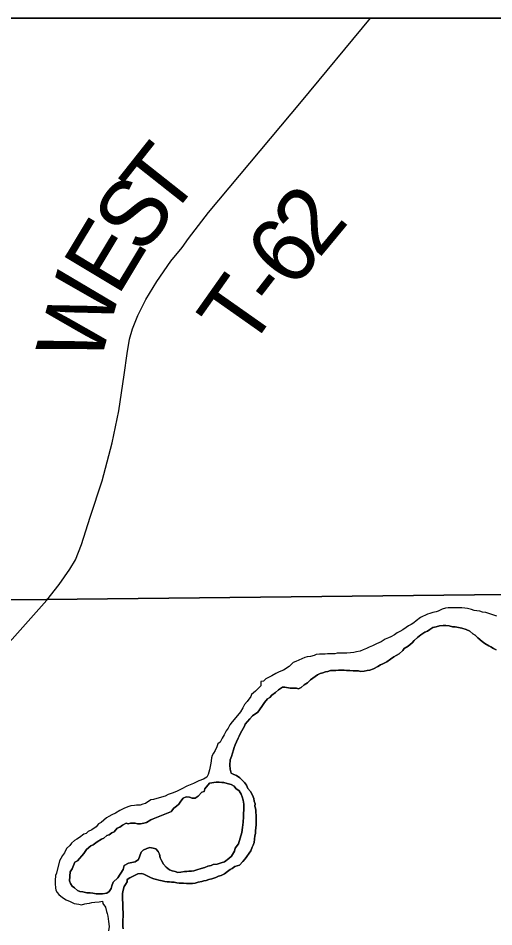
# Model space of a CAD drawing. Extents: x 0 to 34, y 0 to 22.
# Drawn here: x 4.009 to 4.417, y 20.12 to 20.9 of the extents above; entities that cross this region are included whole.
import ezdxf

# ---------------------------------------------------------------- set-up
doc = ezdxf.new("R2010")
doc.units = 0
for name, color, linetype in [('GM_X_Corporation', 7, 'Continuous'), ('GM_X_Major_River', 7, 'Continuous'), ('GM_X_Township_Road', 7, 'Continuous'), ('GM_X_Township_Road_Text', 7, 'Continuous'), ('SH_Data', 7, 'Continuous')]:
    doc.layers.add(name, color=color, linetype=linetype)

msp = doc.modelspace()

# ---------------------------------------------------------------- linework, layer by layer
at = {"layer": 'GM_X_Corporation'}
for points in [[(6.97994, 20.9), (2.1, 20.9)], [(6.97994, 20.9), (2.1, 20.9)], [(5.94533, 20.41578), (5.00335, 20.41162), (4.03341, 20.40117), (3.32712, 20.397)], [(3.32712, 20.397), (4.03341, 20.40117), (5.00335, 20.41162), (5.94533, 20.41578)], [(5.94533, 20.41578), (5.00335, 20.41162), (4.03341, 20.40117), (3.32712, 20.397)], [(3.32712, 20.397), (4.03341, 20.40117), (5.00335, 20.41162), (5.94533, 20.41578)]]:
    msp.add_lwpolyline(points, dxfattribs=at)
at = {"layer": 'GM_X_Major_River'}
for points in [[(4.41945, 20.38683), (4.41261, 20.38912), (4.40995, 20.38988), (4.40729, 20.39026), (4.40501, 20.39103), (4.40235, 20.39141), (4.40007, 20.39179), (4.39779, 20.39255), (4.39437, 20.39332), (4.3921, 20.3937), (4.38944, 20.39408), (4.38374, 20.39409), (4.38146, 20.39409), (4.37766, 20.39409), (4.37538, 20.39372), (4.37272, 20.39295), (4.36929, 20.39106), (4.3674, 20.39068), (4.36473, 20.38992), (4.36207, 20.38916), (4.36017, 20.3884), (4.35409, 20.38575), (4.35029, 20.38271), (4.34838, 20.38119), (4.3461, 20.37967), (4.34382, 20.37853), (4.34192, 20.37701)], [(4.41945, 20.38683), (4.41261, 20.38912), (4.40995, 20.38988), (4.40729, 20.39026), (4.40501, 20.39103), (4.40235, 20.39141), (4.40007, 20.39179), (4.39779, 20.39255), (4.39437, 20.39332), (4.3921, 20.3937), (4.38944, 20.39408), (4.38374, 20.39409), (4.38146, 20.39409), (4.37766, 20.39409), (4.37538, 20.39372), (4.37272, 20.39295), (4.36929, 20.39106), (4.3674, 20.39068), (4.36473, 20.38992), (4.36207, 20.38916), (4.36017, 20.3884), (4.35409, 20.38575), (4.35029, 20.38271), (4.34838, 20.38119), (4.3461, 20.37967), (4.34382, 20.37853), (4.34192, 20.37701)], [(4.34192, 20.37701), (4.33888, 20.37511), (4.33622, 20.37359), (4.33394, 20.37245), (4.33166, 20.37093), (4.32862, 20.36903), (4.32671, 20.36827), (4.32367, 20.36713), (4.32025, 20.36486), (4.31645, 20.36296), (4.31303, 20.36144), (4.30998, 20.3603), (4.3077, 20.35916), (4.30504, 20.35802), (4.30238, 20.35688), (4.29934, 20.35612), (4.29706, 20.35575), (4.29402, 20.35537), (4.29098, 20.35499), (4.28794, 20.35499), (4.2849, 20.35499), (4.28262, 20.355), (4.28072, 20.35462), (4.27654, 20.35462), (4.27426, 20.35462), (4.27236, 20.35424), (4.27046, 20.35425), (4.26742, 20.35425), (4.26476, 20.35387), (4.26286, 20.35311), (4.25982, 20.35235), (4.25678, 20.35198), (4.25488, 20.35122), (4.24728, 20.3478), (4.245, 20.34704), (4.24157, 20.34362), (4.23663, 20.34058), (4.23283, 20.33907), (4.23017, 20.33755), (4.22674, 20.33565), (4.2237, 20.33413), (4.22142, 20.33299), (4.21952, 20.33109), (4.21724, 20.33071), (4.21724, 20.32691), (4.21267, 20.32235), (4.20925, 20.31969), (4.20849, 20.31779), (4.20544, 20.31361), (4.20316, 20.31094), (4.20164, 20.30828), (4.19973, 20.30486), (4.19707, 20.30144), (4.19251, 20.29612), (4.1906, 20.29346), (4.18908, 20.2908), (4.18756, 20.28852), (4.18565, 20.2851), (4.18413, 20.28205), (4.18223, 20.27863), (4.18032, 20.27712), (4.17956, 20.27483), (4.17804, 20.27141), (4.17652, 20.26913), (4.17537, 20.26723), (4.17499, 20.26533), (4.17461, 20.26267), (4.17423, 20.26077), (4.17308, 20.25506), (4.17194, 20.25088), (4.17079, 20.2486), (4.16813, 20.24708), (4.16395, 20.24556), (4.15939, 20.24328), (4.15369, 20.24101), (4.14951, 20.23873), (4.14494, 20.23645), (4.14114, 20.23493), (4.13772, 20.23379), (4.13506, 20.23227), (4.13202, 20.23151), (4.12518, 20.22962), (4.1229, 20.22924), (4.11833, 20.2262), (4.11605, 20.22544), (4.11377, 20.22469), (4.11073, 20.22469), (4.10883, 20.22431), (4.10579, 20.22393), (4.10313, 20.22317), (4.09971, 20.22165), (4.09629, 20.22014), (4.09249, 20.21786), (4.08944, 20.21634), (4.08678, 20.21482), (4.08488, 20.21368), (4.0826, 20.21178), (4.08032, 20.20988), (4.07804, 20.20874), (4.07613, 20.20608), (4.07233, 20.20342)], [(4.34192, 20.37701), (4.33888, 20.37511), (4.33622, 20.37359), (4.33394, 20.37245), (4.33166, 20.37093), (4.32862, 20.36903), (4.32671, 20.36827), (4.32367, 20.36713), (4.32025, 20.36486), (4.31645, 20.36296), (4.31303, 20.36144), (4.30998, 20.3603), (4.3077, 20.35916), (4.30504, 20.35802), (4.30238, 20.35688), (4.29934, 20.35612), (4.29706, 20.35575), (4.29402, 20.35537), (4.29098, 20.35499), (4.28794, 20.35499), (4.2849, 20.35499), (4.28262, 20.355), (4.28072, 20.35462), (4.27654, 20.35462), (4.27426, 20.35462), (4.27236, 20.35424), (4.27046, 20.35425), (4.26742, 20.35425), (4.26476, 20.35387), (4.26286, 20.35311), (4.25982, 20.35235), (4.25678, 20.35198), (4.25488, 20.35122), (4.24728, 20.3478), (4.245, 20.34704), (4.24157, 20.34362), (4.23663, 20.34058), (4.23283, 20.33907), (4.23017, 20.33755), (4.22674, 20.33565), (4.2237, 20.33413), (4.22142, 20.33299), (4.21952, 20.33109), (4.21724, 20.33071), (4.21724, 20.32691), (4.21267, 20.32235), (4.20925, 20.31969), (4.20849, 20.31779), (4.20544, 20.31361), (4.20316, 20.31094), (4.20164, 20.30828), (4.19973, 20.30486), (4.19707, 20.30144), (4.19251, 20.29612), (4.1906, 20.29346), (4.18908, 20.2908), (4.18756, 20.28852), (4.18565, 20.2851), (4.18413, 20.28205), (4.18223, 20.27863), (4.18032, 20.27712), (4.17956, 20.27483), (4.17804, 20.27141), (4.17652, 20.26913), (4.17537, 20.26723), (4.17499, 20.26533), (4.17461, 20.26267), (4.17423, 20.26077), (4.17308, 20.25506), (4.17194, 20.25088), (4.17079, 20.2486), (4.16813, 20.24708), (4.16395, 20.24556), (4.15939, 20.24328), (4.15369, 20.24101), (4.14951, 20.23873), (4.14494, 20.23645), (4.14114, 20.23493), (4.13772, 20.23379), (4.13506, 20.23227), (4.13202, 20.23151), (4.12518, 20.22962), (4.1229, 20.22924), (4.11833, 20.2262), (4.11605, 20.22544), (4.11377, 20.22469), (4.11073, 20.22469), (4.10883, 20.22431), (4.10579, 20.22393), (4.10313, 20.22317), (4.09971, 20.22165), (4.09629, 20.22014), (4.09249, 20.21786), (4.08944, 20.21634), (4.08678, 20.21482), (4.08488, 20.21368), (4.0826, 20.21178), (4.08032, 20.20988), (4.07804, 20.20874), (4.07613, 20.20608), (4.07233, 20.20342)], [(4.26588, 20.33637), (4.26816, 20.33751), (4.27044, 20.33827), (4.27272, 20.33903), (4.27462, 20.33941), (4.27691, 20.34017), (4.2788, 20.34017), (4.28147, 20.34017), (4.28375, 20.34055), (4.28602, 20.34054), (4.28869, 20.34054), (4.29058, 20.34016), (4.29363, 20.34015), (4.29628, 20.33977), (4.29856, 20.33977), (4.30084, 20.33977), (4.30274, 20.33939), (4.30578, 20.33976), (4.30844, 20.34014), (4.31072, 20.34052), (4.31376, 20.34166), (4.31757, 20.34356), (4.31985, 20.34508), (4.32175, 20.34584), (4.32517, 20.34774), (4.32821, 20.35002), (4.33126, 20.35191), (4.33316, 20.35305), (4.33582, 20.35457), (4.33886, 20.35723), (4.34, 20.35913), (4.34342, 20.36103), (4.34685, 20.36407), (4.34875, 20.36597), (4.35141, 20.36863), (4.35445, 20.37091), (4.35788, 20.37319), (4.36015, 20.37395), (4.36206, 20.37547), (4.36472, 20.37699), (4.36738, 20.37775), (4.37042, 20.37851), (4.37346, 20.37888), (4.37574, 20.37888), (4.37878, 20.3785), (4.38144, 20.37773), (4.38372, 20.37773), (4.38676, 20.37697), (4.38942, 20.37659), (4.39322, 20.37544), (4.39625, 20.37392), (4.39891, 20.37164), (4.40081, 20.37049), (4.40309, 20.36821), (4.40688, 20.36516), (4.40916, 20.36326), (4.41258, 20.36136), (4.41448, 20.36059), (4.41676, 20.35907), (4.41903, 20.35793)], [(4.41903, 20.35793), (4.41676, 20.35907), (4.41448, 20.36059), (4.41258, 20.36136), (4.40916, 20.36326), (4.40688, 20.36516), (4.40309, 20.36821), (4.40081, 20.37049), (4.39891, 20.37164), (4.39625, 20.37392), (4.39322, 20.37544), (4.38942, 20.37659), (4.38676, 20.37697), (4.38372, 20.37773), (4.38144, 20.37773), (4.37878, 20.3785), (4.37574, 20.37888), (4.37346, 20.37888), (4.37042, 20.37851), (4.36738, 20.37775), (4.36472, 20.37699), (4.36206, 20.37547), (4.36015, 20.37395), (4.35788, 20.37319), (4.35445, 20.37091), (4.35141, 20.36863), (4.34875, 20.36597), (4.34685, 20.36407), (4.34342, 20.36103), (4.34, 20.35913), (4.33886, 20.35723), (4.33582, 20.35457), (4.33316, 20.35305), (4.33126, 20.35191), (4.32821, 20.35002), (4.32517, 20.34774), (4.32175, 20.34584), (4.31985, 20.34508), (4.31757, 20.34356), (4.31376, 20.34166), (4.31072, 20.34052), (4.30844, 20.34014), (4.30578, 20.33976), (4.30274, 20.33939), (4.30084, 20.33977), (4.29856, 20.33977), (4.29628, 20.33977), (4.29363, 20.34015), (4.29058, 20.34016), (4.28869, 20.34054), (4.28602, 20.34054), (4.28375, 20.34055), (4.28147, 20.34017), (4.2788, 20.34017), (4.27691, 20.34017), (4.27462, 20.33941), (4.27272, 20.33903), (4.27044, 20.33827), (4.26816, 20.33751), (4.26588, 20.33637)], [(4.12548, 20.16154), (4.12776, 20.16078), (4.12966, 20.1604), (4.1327, 20.15963), (4.13498, 20.15925), (4.13688, 20.15887), (4.13878, 20.15887), (4.14068, 20.15849), (4.14296, 20.15848), (4.14524, 20.1581), (4.14714, 20.15772), (4.14904, 20.15772), (4.15094, 20.15772), (4.1536, 20.15733), (4.15664, 20.15733), (4.15854, 20.15733), (4.16082, 20.15771), (4.16348, 20.15847), (4.16652, 20.15923), (4.16842, 20.1596), (4.17032, 20.15998), (4.1726, 20.16074), (4.17526, 20.1615), (4.17868, 20.16264), (4.18096, 20.16378), (4.18324, 20.16416), (4.1859, 20.16568), (4.18857, 20.16758), (4.19085, 20.16947), (4.19275, 20.17023), (4.19503, 20.17213), (4.19883, 20.17327), (4.20187, 20.17631), (4.20378, 20.17859), (4.20872, 20.18543), (4.20987, 20.18848), (4.21063, 20.19037), (4.21139, 20.19266), (4.21177, 20.19532), (4.21216, 20.19836), (4.21254, 20.20026), (4.21254, 20.20255), (4.21292, 20.20521), (4.21331, 20.20787), (4.21331, 20.21167), (4.21331, 20.21433), (4.21332, 20.21624), (4.21294, 20.21814), (4.21294, 20.22004), (4.21256, 20.22194), (4.21218, 20.22384), (4.21219, 20.22575), (4.21143, 20.22803), (4.21105, 20.23031), (4.20992, 20.23335), (4.2084, 20.2364), (4.20612, 20.23906), (4.20498, 20.24173), (4.20309, 20.24401), (4.20157, 20.24591), (4.19929, 20.24819), (4.19625, 20.2501), (4.19397, 20.25086), (4.1917, 20.25201), (4.19094, 20.25543), (4.19056, 20.25885), (4.19095, 20.26341), (4.19209, 20.26646), (4.19362, 20.27216), (4.19438, 20.27406), (4.19514, 20.27634), (4.19629, 20.279), (4.19781, 20.28205), (4.19857, 20.28395), (4.19933, 20.28585), (4.20086, 20.28851), (4.202, 20.29041), (4.20314, 20.29231), (4.2039, 20.29421), (4.20771, 20.29877), (4.20999, 20.30143), (4.21455, 20.30447), (4.21798, 20.30941), (4.22026, 20.31283), (4.22292, 20.31587), (4.22482, 20.31701), (4.22673, 20.31891), (4.22977, 20.32119), (4.23243, 20.32347), (4.23585, 20.32575), (4.23775, 20.32575), (4.24231, 20.32498), (4.24459, 20.32498), (4.24763, 20.32498), (4.24953, 20.3246), (4.25181, 20.32574), (4.25447, 20.32802), (4.25714, 20.32954), (4.2598, 20.3322), (4.2617, 20.33372), (4.26588, 20.33637)], [(4.26588, 20.33637), (4.2617, 20.33372), (4.2598, 20.3322), (4.25714, 20.32954), (4.25447, 20.32802), (4.25181, 20.32574), (4.24953, 20.3246), (4.24763, 20.32498), (4.24459, 20.32498), (4.24231, 20.32498), (4.23775, 20.32575), (4.23585, 20.32575), (4.23243, 20.32347), (4.22977, 20.32119), (4.22673, 20.31891), (4.22482, 20.31701), (4.22292, 20.31587), (4.22026, 20.31283), (4.21798, 20.30941), (4.21455, 20.30447), (4.20999, 20.30143), (4.20771, 20.29877), (4.2039, 20.29421), (4.20314, 20.29231), (4.202, 20.29041), (4.20086, 20.28851), (4.19933, 20.28585), (4.19857, 20.28395), (4.19781, 20.28205), (4.19629, 20.279), (4.19514, 20.27634), (4.19438, 20.27406), (4.19362, 20.27216), (4.19209, 20.26646), (4.19095, 20.26341), (4.19056, 20.25885), (4.19094, 20.25543), (4.1917, 20.25201), (4.19397, 20.25086), (4.19625, 20.2501), (4.19929, 20.24819), (4.20157, 20.24591), (4.20309, 20.24401), (4.20498, 20.24173), (4.20612, 20.23906), (4.2084, 20.2364), (4.20992, 20.23335), (4.21105, 20.23031), (4.21143, 20.22803), (4.21219, 20.22575), (4.21218, 20.22384), (4.21256, 20.22194), (4.21294, 20.22004), (4.21294, 20.21814), (4.21332, 20.21624), (4.21331, 20.21433), (4.21331, 20.21167), (4.21331, 20.20787), (4.21292, 20.20521), (4.21254, 20.20255), (4.21254, 20.20026), (4.21216, 20.19836), (4.21177, 20.19532), (4.21139, 20.19266), (4.21063, 20.19037), (4.20987, 20.18848), (4.20872, 20.18543), (4.20378, 20.17859), (4.20187, 20.17631), (4.19883, 20.17327), (4.19503, 20.17213), (4.19275, 20.17023), (4.19085, 20.16947), (4.18857, 20.16758), (4.1859, 20.16568), (4.18324, 20.16416), (4.18096, 20.16378), (4.17868, 20.16264), (4.17526, 20.1615), (4.1726, 20.16074), (4.17032, 20.15998), (4.16842, 20.1596), (4.16652, 20.15923), (4.16348, 20.15847), (4.16082, 20.15771), (4.15854, 20.15733), (4.15664, 20.15733), (4.1536, 20.15733), (4.15094, 20.15772), (4.14904, 20.15772), (4.14714, 20.15772), (4.14524, 20.1581), (4.14296, 20.15848), (4.14068, 20.15849), (4.13878, 20.15887), (4.13688, 20.15887), (4.13498, 20.15925), (4.1327, 20.15963), (4.12966, 20.1604), (4.12776, 20.16078), (4.12548, 20.16154)], [(4.1035, 20.20872), (4.1016, 20.2091), (4.09856, 20.20758), (4.09627, 20.20568), (4.09399, 20.20492), (4.09133, 20.20188), (4.08943, 20.20075), (4.08715, 20.19923), (4.08525, 20.19847), (4.08258, 20.19619), (4.08068, 20.19543), (4.07688, 20.19315), (4.07346, 20.19049), (4.07156, 20.18973), (4.06776, 20.18669), (4.06547, 20.18327), (4.06014, 20.17681), (4.05786, 20.17567), (4.05558, 20.16997), (4.05367, 20.16731), (4.05329, 20.1597), (4.05404, 20.15742), (4.05556, 20.15513), (4.05746, 20.15361), (4.06012, 20.15133), (4.06202, 20.15056), (4.06467, 20.15018), (4.06809, 20.14942), (4.07075, 20.14942), (4.07303, 20.14903), (4.07607, 20.14865), (4.07835, 20.14865), (4.08139, 20.14865), (4.08519, 20.14902), (4.08709, 20.15054), (4.089, 20.1532), (4.08938, 20.15549), (4.09052, 20.15853), (4.09471, 20.16233), (4.09927, 20.16955), (4.10004, 20.17297), (4.10384, 20.17487), (4.10954, 20.17601), (4.1122, 20.17791), (4.11449, 20.18437), (4.11639, 20.18589), (4.11943, 20.18741), (4.12209, 20.18817), (4.12475, 20.18779), (4.12703, 20.18702), (4.12931, 20.18474), (4.13044, 20.18246), (4.13082, 20.17941), (4.13196, 20.17713), (4.13386, 20.17408), (4.13613, 20.17142), (4.13879, 20.16914), (4.14107, 20.16837), (4.14373, 20.16761), (4.14601, 20.16685), (4.14867, 20.16723), (4.15171, 20.1676), (4.15361, 20.1676), (4.15551, 20.16798), (4.15779, 20.16798), (4.15969, 20.16836), (4.16235, 20.16912), (4.16615, 20.17026), (4.16919, 20.17101), (4.17185, 20.17215), (4.17451, 20.17291), (4.17641, 20.17367), (4.17983, 20.17405), (4.18325, 20.17519), (4.18591, 20.17594), (4.18972, 20.17898), (4.192, 20.18088), (4.19466, 20.18506), (4.19505, 20.18773), (4.19809, 20.19153), (4.20076, 20.20103), (4.20153, 20.2056), (4.20191, 20.21016), (4.2023, 20.21472), (4.2023, 20.21701), (4.20268, 20.22119), (4.20269, 20.22537), (4.20193, 20.2288), (4.20117, 20.23184), (4.20042, 20.23412), (4.19852, 20.23679), (4.19586, 20.23907), (4.19434, 20.24097), (4.19169, 20.2425), (4.18827, 20.24326), (4.18561, 20.24402), (4.18371, 20.24402), (4.18143, 20.2444), (4.17991, 20.24441), (4.17877, 20.24441)], [(4.17877, 20.24441), (4.17991, 20.24441), (4.18143, 20.2444), (4.18371, 20.24402), (4.18561, 20.24402), (4.18827, 20.24326), (4.19169, 20.2425), (4.19434, 20.24097), (4.19586, 20.23907), (4.19852, 20.23679), (4.20042, 20.23412), (4.20117, 20.23184), (4.20193, 20.2288), (4.20269, 20.22537), (4.20268, 20.22119), (4.2023, 20.21701), (4.2023, 20.21472), (4.20191, 20.21016), (4.20153, 20.2056), (4.20076, 20.20103), (4.19809, 20.19153), (4.19505, 20.18773), (4.19466, 20.18506), (4.192, 20.18088), (4.18972, 20.17898), (4.18591, 20.17594), (4.18325, 20.17519), (4.17983, 20.17405), (4.17641, 20.17367), (4.17451, 20.17291), (4.17185, 20.17215), (4.16919, 20.17101), (4.16615, 20.17026), (4.16235, 20.16912), (4.15969, 20.16836), (4.15779, 20.16798), (4.15551, 20.16798), (4.15361, 20.1676), (4.15171, 20.1676), (4.14867, 20.16723), (4.14601, 20.16685), (4.14373, 20.16761), (4.14107, 20.16837), (4.13879, 20.16914), (4.13613, 20.17142), (4.13386, 20.17408), (4.13196, 20.17713), (4.13082, 20.17941), (4.13044, 20.18246), (4.12931, 20.18474), (4.12703, 20.18702), (4.12475, 20.18779), (4.12209, 20.18817), (4.11943, 20.18741), (4.11639, 20.18589), (4.11449, 20.18437), (4.1122, 20.17791), (4.10954, 20.17601), (4.10384, 20.17487), (4.10004, 20.17297), (4.09927, 20.16955), (4.09471, 20.16233), (4.09052, 20.15853), (4.08938, 20.15549), (4.089, 20.1532), (4.08709, 20.15054), (4.08519, 20.14902), (4.08139, 20.14865), (4.07835, 20.14865), (4.07607, 20.14865), (4.07303, 20.14903), (4.07075, 20.14942), (4.06809, 20.14942), (4.06467, 20.15018), (4.06202, 20.15056), (4.06012, 20.15133), (4.05746, 20.15361), (4.05556, 20.15513), (4.05404, 20.15742), (4.05329, 20.1597), (4.05367, 20.16731), (4.05558, 20.16997), (4.05786, 20.17567), (4.06014, 20.17681), (4.06547, 20.18327), (4.06776, 20.18669), (4.07156, 20.18973), (4.07346, 20.19049), (4.07688, 20.19315), (4.08068, 20.19543), (4.08258, 20.19619), (4.08525, 20.19847), (4.08715, 20.19923), (4.08943, 20.20075), (4.09133, 20.20188), (4.09399, 20.20492), (4.09627, 20.20568), (4.09856, 20.20758), (4.1016, 20.2091), (4.1035, 20.20872)], [(4.17877, 20.24441), (4.17307, 20.24365), (4.16926, 20.23871), (4.1685, 20.23643), (4.1666, 20.23567), (4.16356, 20.23225), (4.1609, 20.23073), (4.15823, 20.23073), (4.15596, 20.2315), (4.1533, 20.23188), (4.15064, 20.23074), (4.14873, 20.22808), (4.14683, 20.22542), (4.14493, 20.2239), (4.14265, 20.222), (4.14074, 20.21934), (4.14056, 20.21923)], [(4.14056, 20.21923), (4.14074, 20.21934), (4.14265, 20.222), (4.14493, 20.2239), (4.14683, 20.22542), (4.14873, 20.22808), (4.15064, 20.23074), (4.1533, 20.23188), (4.15596, 20.2315), (4.15823, 20.23073), (4.1609, 20.23073), (4.16356, 20.23225), (4.1666, 20.23567), (4.1685, 20.23643), (4.16926, 20.23871), (4.17307, 20.24365), (4.17877, 20.24441)], [(4.14056, 20.21923), (4.12478, 20.21289), (4.12288, 20.21213), (4.11908, 20.20985), (4.1168, 20.20909), (4.11414, 20.20871), (4.11147, 20.20871), (4.10958, 20.20909), (4.1073, 20.2091), (4.1054, 20.2091), (4.1035, 20.20872)], [(4.1035, 20.20872), (4.1054, 20.2091), (4.1073, 20.2091), (4.10958, 20.20909), (4.11147, 20.20871), (4.11414, 20.20871), (4.1168, 20.20909), (4.11908, 20.20985), (4.12288, 20.21213), (4.12478, 20.21289), (4.14056, 20.21923)], [(4.07233, 20.20342), (4.06929, 20.2019), (4.06739, 20.20038), (4.06549, 20.19962), (4.06169, 20.19696), (4.0594, 20.19544), (4.0575, 20.1943), (4.05484, 20.19203), (4.05332, 20.19012), (4.05066, 20.18746), (4.04875, 20.18366), (4.04723, 20.18138), (4.04571, 20.17872), (4.04457, 20.17682), (4.04189, 20.16617), (4.04113, 20.16427), (4.04075, 20.16009), (4.04074, 20.15705), (4.04112, 20.15362), (4.0415, 20.15172), (4.04264, 20.14982), (4.04415, 20.14792), (4.04719, 20.14525), (4.05023, 20.14335), (4.05365, 20.14182), (4.05707, 20.1403), (4.06124, 20.13954), (4.06352, 20.13915), (4.06618, 20.13991), (4.06808, 20.14029), (4.07037, 20.14067), (4.07226, 20.14105), (4.07493, 20.14143), (4.07872, 20.1418), (4.08139, 20.14218), (4.08176, 20.14028), (4.08404, 20.13723), (4.0848, 20.13343), (4.08555, 20.13153), (4.08593, 20.12925), (4.08631, 20.12696), (4.08669, 20.12468), (4.08706, 20.1205), (4.08668, 20.11669)], [(4.07233, 20.20342), (4.06929, 20.2019), (4.06739, 20.20038), (4.06549, 20.19962), (4.06169, 20.19696), (4.0594, 20.19544), (4.0575, 20.1943), (4.05484, 20.19203), (4.05332, 20.19012), (4.05066, 20.18746), (4.04875, 20.18366), (4.04723, 20.18138), (4.04571, 20.17872), (4.04457, 20.17682), (4.04189, 20.16617), (4.04113, 20.16427), (4.04075, 20.16009), (4.04074, 20.15705), (4.04112, 20.15362), (4.0415, 20.15172), (4.04264, 20.14982), (4.04415, 20.14792), (4.04719, 20.14525), (4.05023, 20.14335), (4.05365, 20.14182), (4.05707, 20.1403), (4.06124, 20.13954), (4.06352, 20.13915), (4.06618, 20.13991), (4.06808, 20.14029), (4.07037, 20.14067), (4.07226, 20.14105), (4.07493, 20.14143), (4.07872, 20.1418), (4.08139, 20.14218), (4.08176, 20.14028), (4.08404, 20.13723), (4.0848, 20.13343), (4.08555, 20.13153), (4.08593, 20.12925), (4.08631, 20.12696), (4.08669, 20.12468), (4.08706, 20.1205), (4.08668, 20.11669)], [(4.09922, 20.11859), (4.09884, 20.12049), (4.09884, 20.12467), (4.09923, 20.13038), (4.09923, 20.13266), (4.09886, 20.1357), (4.09886, 20.13874), (4.09886, 20.14065), (4.09848, 20.14369), (4.09849, 20.14863), (4.09887, 20.15053), (4.10002, 20.15472), (4.10116, 20.15662), (4.10268, 20.1589), (4.10268, 20.1608), (4.10497, 20.16232), (4.10763, 20.16384), (4.10953, 20.1646), (4.11181, 20.16574), (4.11485, 20.16611), (4.11675, 20.16535), (4.11865, 20.16459), (4.12093, 20.16345), (4.1232, 20.1623), (4.12548, 20.16154)], [(4.12548, 20.16154), (4.1232, 20.1623), (4.12093, 20.16345), (4.11865, 20.16459), (4.11675, 20.16535), (4.11485, 20.16611), (4.11181, 20.16574), (4.10953, 20.1646), (4.10763, 20.16384), (4.10497, 20.16232), (4.10268, 20.1608), (4.10268, 20.1589), (4.10116, 20.15662), (4.10002, 20.15472), (4.09887, 20.15053), (4.09849, 20.14863), (4.09848, 20.14369), (4.09886, 20.14065), (4.09886, 20.13874), (4.09886, 20.1357), (4.09923, 20.13266), (4.09923, 20.13038), (4.09884, 20.12467), (4.09884, 20.12049), (4.09922, 20.11859)]]:
    msp.add_lwpolyline(points, dxfattribs=at)
at = {"layer": 'GM_X_Township_Road'}
for points in [[(4.03363, 20.40062), (4.04429, 20.41406), (4.05348, 20.42709), (4.05821, 20.43522), (4.06354, 20.44841), (4.07094, 20.4718), (4.08117, 20.50301), (4.08983, 20.53569), (4.0955, 20.5631), (4.10016, 20.59383), (4.10258, 20.61228), (4.10453, 20.62442), (4.10709, 20.63328), (4.11168, 20.64475), (4.11874, 20.65861), (4.12792, 20.67398), (4.13999, 20.6914), (4.14981, 20.70319), (4.15526, 20.71103), (4.17232, 20.73313), (4.25202, 20.82851), (4.31124, 20.9)], [(3.587, 19.87766), (3.59832, 19.89128), (3.63661, 19.94339), (3.79742, 20.13645), (3.87514, 20.23153), (3.94088, 20.30057), (4.00413, 20.36713), (4.03363, 20.40062)]]:
    msp.add_lwpolyline(points, dxfattribs=at)
at = {"layer": 'SH_Data'}
msp.add_line((2.1, 20.9), (8.9, 20.9), dxfattribs=at)

# ---------------------------------------------------------------- texts
at = {"layer": 'GM_X_Township_Road_Text'}
for s, rotation, p in [('T', 51.62397, (4.13829, 20.72598)), ('S', 53.25648, (4.11562, 20.6956)), ('2', 50.42663, (4.26677, 20.69305)), ('E', 58.97817, (4.09455, 20.66043)), ('6', 50.94034, (4.2448, 20.66597)), ('W', 74.51254, (4.07858, 20.60071)), ('T', 54.82277, (4.20668, 20.61357)), ('-', 52.36668, (4.23078, 20.64779))]:
    msp.add_text(s, height=0.05682, rotation=rotation, dxfattribs=at).set_placement(p)

doc.saveas('drawing.dxf')
